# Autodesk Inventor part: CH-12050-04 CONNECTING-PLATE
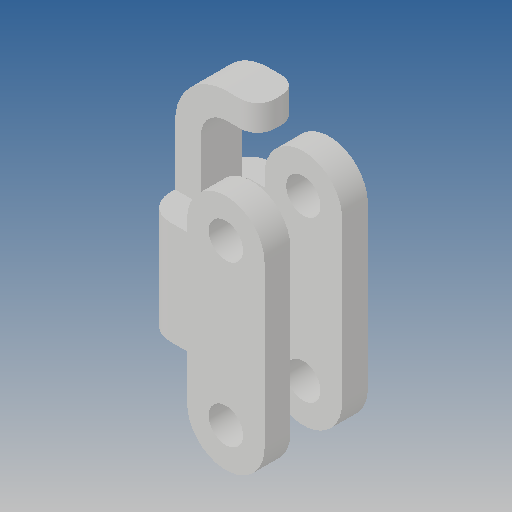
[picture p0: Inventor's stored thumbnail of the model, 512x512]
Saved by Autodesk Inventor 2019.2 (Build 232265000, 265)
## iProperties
Created: 2015-08
Part Number: CH-12050-04 CONNECTING-PLATE
Material: Ogólny
Document SubType Name: Modeling
Designer: CADENGINEERING4
Density: 1 g/cm^3
Appearance: Domyślna
Author: CADENGINEERING4
Revision Number: ÈÎºÎ
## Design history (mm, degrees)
feature "Ô²½Ç2"
node "Bryła1"
